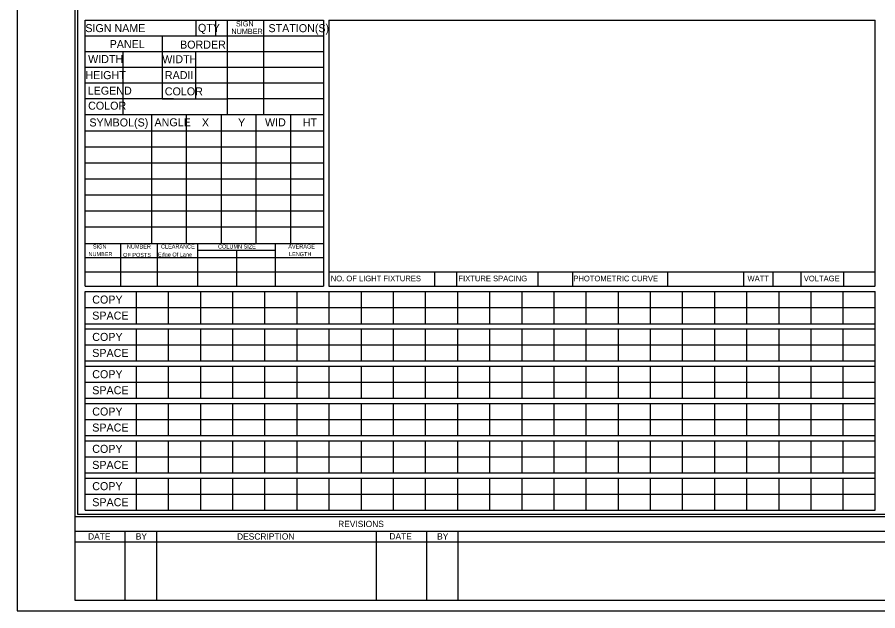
# Model space of a CAD drawing. Extents: x 17890628 to 17891459, y 17897314 to 17897992.
# Drawn here: x 17890701.3 to 17890765.8, y 17897413.7 to 17897458.2 of the extents above; entities that cross this region are included whole.
import ezdxf

# ---------------------------------------------------------------- set-up
doc = ezdxf.new("R2010")
doc.units = 0
for name, color, linetype in [('PlotBorder_dp', 7, 'Continuous'), ('SheetBorder_dp', 7, 'Continuous'), ('SheetLines_dp', 7, 'Continuous'), ('SheetLinesMisc2_dp', 7, 'Continuous'), ('TextMinor', 7, 'Continuous'), ('TextMisc', 7, 'Continuous')]:
    doc.layers.add(name, color=color, linetype=linetype)

msp = doc.modelspace()

# ---------------------------------------------------------------- linework, layer by layer
at = {"layer": 'PlotBorder_dp'}
msp.add_lwpolyline([(17890701.346, 17897413.687), (17890830.745, 17897413.687), (17890830.745, 17897496.818), (17890701.346, 17897496.818)], close=True, dxfattribs=at)
at = {"layer": 'SheetBorder_dp'}
for p, q in [((17890705.659, 17897496.034), (17890705.659, 17897414.472)), ((17890705.659, 17897420.746), (17890826.432, 17897420.746)), ((17890705.659, 17897414.472), (17890826.432, 17897414.472))]:
    msp.add_line(p, q, dxfattribs=at)
at = {"layer": 'SheetLines_dp'}
for p, q in [((17890705.659, 17897419.648), (17890769.182, 17897419.648)), ((17890709.424, 17897419.648), (17890709.424, 17897414.472)), ((17890711.776, 17897419.648), (17890711.776, 17897414.472)), ((17890728.245, 17897419.648), (17890728.245, 17897414.472)), ((17890732.01, 17897419.648), (17890732.01, 17897414.472)), ((17890734.362, 17897419.648), (17890734.362, 17897414.472)), ((17890705.659, 17897418.864), (17890769.182, 17897418.864))]:
    msp.add_line(p, q, dxfattribs=at)
at = {"layer": 'SheetLinesMisc2_dp'}
for p, q in [((17890705.872, 17897495.849), (17890705.872, 17897420.931)), ((17890706.45, 17897438.022), (17890706.45, 17897457.96)), ((17890706.45, 17897457.96), (17890724.295, 17897457.96)), ((17890714.721, 17897457.96), (17890714.721, 17897456.783)), ((17890716.203, 17897457.96), (17890716.203, 17897456.783)), ((17890717.086, 17897457.96), (17890717.086, 17897450.894)), ((17890719.801, 17897457.96), (17890719.801, 17897450.894)), ((17890724.295, 17897457.96), (17890724.295, 17897438.022)), ((17890724.706, 17897457.96), (17890765.638, 17897457.96)), ((17890724.706, 17897457.96), (17890724.706, 17897438.051)), ((17890765.638, 17897438.051), (17890765.638, 17897457.962)), ((17890706.45, 17897456.783), (17890724.295, 17897456.783)), ((17890712.217, 17897456.783), (17890712.217, 17897452.059)), ((17890706.45, 17897455.605), (17890724.295, 17897455.605)), ((17890709.27, 17897455.605), (17890709.27, 17897450.894)), ((17890714.706, 17897455.592), (17890714.706, 17897452.059)), ((17890706.45, 17897454.427), (17890724.295, 17897454.427)), ((17890706.45, 17897453.25), (17890724.295, 17897453.25)), ((17890706.45, 17897452.072), (17890713.068, 17897452.072)), ((17890712.217, 17897452.059), (17890717.086, 17897452.059)), ((17890717.086, 17897452.072), (17890724.295, 17897452.072)), ((17890706.45, 17897450.894), (17890724.295, 17897450.894)), ((17890711.405, 17897450.871), (17890711.405, 17897441.227)), ((17890714.013, 17897450.871), (17890714.013, 17897441.227)), ((17890716.62, 17897450.871), (17890716.62, 17897441.227)), ((17890719.228, 17897450.871), (17890719.228, 17897441.227)), ((17890721.835, 17897450.871), (17890721.835, 17897441.138)), ((17890706.454, 17897449.668), (17890724.295, 17897449.668)), ((17890706.454, 17897448.466), (17890724.295, 17897448.466)), ((17890706.454, 17897447.263), (17890724.295, 17897447.263)), ((17890706.454, 17897446.061), (17890724.295, 17897446.061)), ((17890706.454, 17897444.861), (17890724.295, 17897444.861)), ((17890706.454, 17897443.661), (17890724.295, 17897443.661)), ((17890706.454, 17897442.461), (17890724.295, 17897442.461)), ((17890706.45, 17897441.227), (17890724.295, 17897441.227)), ((17890706.45, 17897441.227), (17890724.295, 17897441.227)), ((17890709.098, 17897441.227), (17890709.098, 17897438.022)), ((17890711.835, 17897441.227), (17890711.835, 17897438.022)), ((17890714.857, 17897441.227), (17890714.857, 17897438.022)), ((17890720.676, 17897441.227), (17890720.676, 17897438.022)), ((17890714.857, 17897440.717), (17890720.672, 17897440.717)), ((17890717.778, 17897440.717), (17890717.778, 17897438.022)), ((17890706.45, 17897440.159), (17890724.295, 17897440.159)), ((17890706.45, 17897439.091), (17890724.295, 17897439.091)), ((17890724.706, 17897439.091), (17890765.638, 17897439.091)), ((17890732.613, 17897439.091), (17890732.613, 17897438.023)), ((17890734.269, 17897439.091), (17890734.269, 17897438.023)), ((17890740.364, 17897439.091), (17890740.364, 17897438.023)), ((17890742.958, 17897439.091), (17890742.958, 17897438.023)), ((17890750.085, 17897439.091), (17890750.085, 17897438.023)), ((17890755.773, 17897439.091), (17890755.773, 17897438.023)), ((17890757.969, 17897439.091), (17890757.969, 17897438.023)), ((17890760.087, 17897439.091), (17890760.087, 17897438.023)), ((17890763.275, 17897439.091), (17890763.275, 17897438.023)), ((17890706.45, 17897438.022), (17890724.295, 17897438.022)), ((17890724.706, 17897438.051), (17890724.706, 17897438.024)), ((17890724.706, 17897438.023), (17890765.638, 17897438.023)), ((17890706.449, 17897437.612), (17890765.638, 17897437.612)), ((17890706.449, 17897421.223), (17890706.449, 17897437.612)), ((17890710.259, 17897437.612), (17890710.259, 17897435.207)), ((17890712.668, 17897437.612), (17890712.668, 17897435.207)), ((17890715.075, 17897437.612), (17890715.075, 17897435.207)), ((17890717.483, 17897437.612), (17890717.483, 17897435.207)), ((17890719.89, 17897437.612), (17890719.89, 17897435.207)), ((17890722.298, 17897437.612), (17890722.298, 17897435.207)), ((17890724.706, 17897437.612), (17890724.706, 17897435.207)), ((17890727.114, 17897437.612), (17890727.114, 17897435.207)), ((17890729.521, 17897437.612), (17890729.521, 17897435.207)), ((17890731.929, 17897437.612), (17890731.929, 17897435.207)), ((17890734.337, 17897437.612), (17890734.337, 17897435.207)), ((17890736.745, 17897437.612), (17890736.745, 17897435.207)), ((17890739.153, 17897437.612), (17890739.153, 17897435.207)), ((17890741.56, 17897437.612), (17890741.56, 17897435.207)), ((17890743.969, 17897437.612), (17890743.969, 17897435.207)), ((17890746.376, 17897437.612), (17890746.376, 17897435.207)), ((17890748.784, 17897437.612), (17890748.784, 17897435.207)), ((17890751.191, 17897437.612), (17890751.191, 17897435.207)), ((17890753.6, 17897437.612), (17890753.6, 17897435.207)), ((17890756.007, 17897437.612), (17890756.007, 17897435.207)), ((17890758.415, 17897437.612), (17890758.415, 17897435.207)), ((17890760.822, 17897437.612), (17890760.822, 17897435.207)), ((17890763.231, 17897437.612), (17890763.231, 17897435.207)), ((17890765.638, 17897421.223), (17890765.638, 17897437.612)), ((17890706.449, 17897436.411), (17890765.638, 17897436.411)), ((17890706.449, 17897435.207), (17890765.638, 17897435.207)), ((17890706.449, 17897434.815), (17890765.638, 17897434.815)), ((17890710.259, 17897434.815), (17890710.259, 17897432.41)), ((17890712.668, 17897434.815), (17890712.668, 17897432.41)), ((17890715.075, 17897434.815), (17890715.075, 17897432.41)), ((17890717.483, 17897434.815), (17890717.483, 17897432.41)), ((17890719.89, 17897434.815), (17890719.89, 17897432.41)), ((17890722.298, 17897434.815), (17890722.298, 17897432.41)), ((17890724.706, 17897434.815), (17890724.706, 17897432.41)), ((17890727.114, 17897434.815), (17890727.114, 17897432.41)), ((17890729.521, 17897434.815), (17890729.521, 17897432.41)), ((17890731.929, 17897434.815), (17890731.929, 17897432.41)), ((17890734.337, 17897434.815), (17890734.337, 17897432.41)), ((17890736.745, 17897434.815), (17890736.745, 17897432.41)), ((17890739.153, 17897434.815), (17890739.153, 17897432.41)), ((17890741.56, 17897434.815), (17890741.56, 17897432.41)), ((17890743.969, 17897434.815), (17890743.969, 17897432.41)), ((17890746.376, 17897434.815), (17890746.376, 17897432.41)), ((17890748.784, 17897434.815), (17890748.784, 17897432.41)), ((17890751.191, 17897434.815), (17890751.191, 17897432.41)), ((17890753.6, 17897434.815), (17890753.6, 17897432.41)), ((17890756.007, 17897434.815), (17890756.007, 17897432.41)), ((17890758.415, 17897434.815), (17890758.415, 17897432.41)), ((17890760.822, 17897434.815), (17890760.822, 17897432.41)), ((17890763.231, 17897434.815), (17890763.231, 17897432.41)), ((17890706.449, 17897433.613), (17890765.638, 17897433.613)), ((17890706.449, 17897432.41), (17890765.638, 17897432.41)), ((17890706.449, 17897432.018), (17890765.638, 17897432.018)), ((17890710.259, 17897432.018), (17890710.259, 17897429.614)), ((17890712.668, 17897432.018), (17890712.668, 17897429.614)), ((17890715.075, 17897432.018), (17890715.075, 17897429.614)), ((17890717.483, 17897432.018), (17890717.483, 17897429.614)), ((17890719.89, 17897432.018), (17890719.89, 17897429.614)), ((17890722.298, 17897432.018), (17890722.298, 17897429.614)), ((17890724.706, 17897432.018), (17890724.706, 17897429.614)), ((17890727.114, 17897432.018), (17890727.114, 17897429.614)), ((17890729.521, 17897432.018), (17890729.521, 17897429.614)), ((17890731.929, 17897432.018), (17890731.929, 17897429.614)), ((17890734.337, 17897432.018), (17890734.337, 17897429.614)), ((17890736.745, 17897432.018), (17890736.745, 17897429.614)), ((17890739.153, 17897432.018), (17890739.153, 17897429.614)), ((17890741.56, 17897432.018), (17890741.56, 17897429.614)), ((17890743.969, 17897432.018), (17890743.969, 17897429.614)), ((17890746.376, 17897432.018), (17890746.376, 17897429.614)), ((17890748.784, 17897432.018), (17890748.784, 17897429.614)), ((17890751.191, 17897432.018), (17890751.191, 17897429.614)), ((17890753.6, 17897432.018), (17890753.6, 17897429.614)), ((17890756.007, 17897432.018), (17890756.007, 17897429.614)), ((17890758.415, 17897432.018), (17890758.415, 17897429.614)), ((17890760.822, 17897432.018), (17890760.822, 17897429.614)), ((17890763.231, 17897432.018), (17890763.231, 17897429.614)), ((17890706.449, 17897430.816), (17890765.638, 17897430.816)), ((17890706.449, 17897429.614), (17890765.638, 17897429.614)), ((17890706.449, 17897429.221), (17890765.638, 17897429.221)), ((17890710.259, 17897429.221), (17890710.259, 17897426.817)), ((17890712.668, 17897429.221), (17890712.668, 17897426.817)), ((17890715.075, 17897429.221), (17890715.075, 17897426.817)), ((17890717.483, 17897429.221), (17890717.483, 17897426.817)), ((17890719.89, 17897429.221), (17890719.89, 17897426.817)), ((17890722.298, 17897429.221), (17890722.298, 17897426.817)), ((17890724.706, 17897429.221), (17890724.706, 17897426.817)), ((17890727.114, 17897429.221), (17890727.114, 17897426.817)), ((17890729.521, 17897429.221), (17890729.521, 17897426.817)), ((17890731.929, 17897429.221), (17890731.929, 17897426.817)), ((17890734.337, 17897429.221), (17890734.337, 17897426.817)), ((17890736.745, 17897429.221), (17890736.745, 17897426.817)), ((17890739.153, 17897429.221), (17890739.153, 17897426.817)), ((17890741.56, 17897429.221), (17890741.56, 17897426.817)), ((17890743.969, 17897429.221), (17890743.969, 17897426.817)), ((17890746.376, 17897429.221), (17890746.376, 17897426.817)), ((17890748.784, 17897429.221), (17890748.784, 17897426.817)), ((17890751.191, 17897429.221), (17890751.191, 17897426.817)), ((17890753.6, 17897429.221), (17890753.6, 17897426.817)), ((17890756.007, 17897429.221), (17890756.007, 17897426.817)), ((17890758.415, 17897429.221), (17890758.415, 17897426.817)), ((17890760.822, 17897429.221), (17890760.822, 17897426.817)), ((17890763.231, 17897429.221), (17890763.231, 17897426.817)), ((17890706.449, 17897428.02), (17890765.638, 17897428.02)), ((17890706.449, 17897426.817), (17890765.638, 17897426.817)), ((17890706.449, 17897426.424), (17890765.638, 17897426.424)), ((17890710.259, 17897426.424), (17890710.259, 17897424.02)), ((17890712.668, 17897426.424), (17890712.668, 17897424.02)), ((17890715.075, 17897426.424), (17890715.075, 17897424.02)), ((17890717.483, 17897426.424), (17890717.483, 17897424.02)), ((17890719.89, 17897426.424), (17890719.89, 17897424.02)), ((17890722.298, 17897426.424), (17890722.298, 17897424.02)), ((17890724.706, 17897426.424), (17890724.706, 17897424.02)), ((17890727.114, 17897426.424), (17890727.114, 17897424.02)), ((17890729.521, 17897426.424), (17890729.521, 17897424.02)), ((17890731.929, 17897426.424), (17890731.929, 17897424.02)), ((17890734.337, 17897426.424), (17890734.337, 17897424.02)), ((17890736.745, 17897426.424), (17890736.745, 17897424.02)), ((17890739.153, 17897426.424), (17890739.153, 17897424.02)), ((17890741.56, 17897426.424), (17890741.56, 17897424.02)), ((17890743.969, 17897426.424), (17890743.969, 17897424.02)), ((17890746.376, 17897426.424), (17890746.376, 17897424.02)), ((17890748.784, 17897426.424), (17890748.784, 17897424.02)), ((17890751.191, 17897426.424), (17890751.191, 17897424.02)), ((17890753.6, 17897426.424), (17890753.6, 17897424.02)), ((17890756.007, 17897426.424), (17890756.007, 17897424.02)), ((17890758.415, 17897426.424), (17890758.415, 17897424.02)), ((17890760.822, 17897426.424), (17890760.822, 17897424.02)), ((17890763.231, 17897426.424), (17890763.231, 17897424.02)), ((17890706.449, 17897425.222), (17890765.638, 17897425.222)), ((17890706.449, 17897424.02), (17890765.638, 17897424.02)), ((17890706.449, 17897423.628), (17890765.638, 17897423.628)), ((17890710.259, 17897423.628), (17890710.259, 17897421.223)), ((17890712.668, 17897423.628), (17890712.668, 17897421.223)), ((17890715.075, 17897423.628), (17890715.075, 17897421.223)), ((17890717.483, 17897423.628), (17890717.483, 17897421.223)), ((17890719.89, 17897423.628), (17890719.89, 17897421.223)), ((17890722.298, 17897423.628), (17890722.298, 17897421.223)), ((17890724.706, 17897423.628), (17890724.706, 17897421.223)), ((17890727.114, 17897423.628), (17890727.114, 17897421.223)), ((17890729.521, 17897423.628), (17890729.521, 17897421.223)), ((17890731.929, 17897423.628), (17890731.929, 17897421.223)), ((17890734.337, 17897423.628), (17890734.337, 17897421.223)), ((17890736.745, 17897423.628), (17890736.745, 17897421.223)), ((17890739.153, 17897423.628), (17890739.153, 17897421.223)), ((17890741.56, 17897423.628), (17890741.56, 17897421.223)), ((17890743.969, 17897423.628), (17890743.969, 17897421.223)), ((17890746.376, 17897423.628), (17890746.376, 17897421.223)), ((17890748.784, 17897423.628), (17890748.784, 17897421.223)), ((17890751.191, 17897423.628), (17890751.191, 17897421.223)), ((17890753.6, 17897423.628), (17890753.6, 17897421.223)), ((17890756.007, 17897423.628), (17890756.007, 17897421.223)), ((17890758.415, 17897423.628), (17890758.415, 17897421.223)), ((17890760.822, 17897423.628), (17890760.822, 17897421.223)), ((17890763.231, 17897423.628), (17890763.231, 17897421.223)), ((17890706.449, 17897422.425), (17890765.638, 17897422.425)), ((17890705.872, 17897420.931), (17890826.223, 17897420.931)), ((17890706.449, 17897421.223), (17890765.638, 17897421.223))]:
    msp.add_line(p, q, dxfattribs=at)

# ---------------------------------------------------------------- texts
at = {"layer": 'TextMinor'}
for s, height, p in [('SIGN', 0.3921, (17890717.741, 17897457.488)), ('SIGN NAME', 0.5999, (17890706.45, 17897457.059)), ('QTY', 0.5999, (17890714.892, 17897457.078)), ('NUMBER', 0.3921, (17890717.4, 17897456.918)), ('STATION(S)', 0.5999, (17890720.176, 17897457.055)), ('PANEL', 0.5999, (17890708.274, 17897455.862)), ('BORDER', 0.5999, (17890713.551, 17897455.821)), ('WIDTH', 0.5999, (17890706.661, 17897454.741)), ('WIDTH', 0.5999, (17890712.217, 17897454.729)), ('HEIGHT', 0.5999, (17890706.45, 17897453.534)), ('RADII', 0.5999, (17890712.414, 17897453.536)), ('LEGEND', 0.5999, (17890706.63, 17897452.369)), ('COLOR', 0.5999, (17890712.409, 17897452.318)), ('COLOR', 0.5999, (17890706.661, 17897451.245)), ('SYMBOL(S)', 0.5999, (17890706.757, 17897449.987)), ('ANGLE', 0.5999, (17890711.635, 17897449.999)), ('WID', 0.5999, (17890719.916, 17897449.999)), ('X', 0.6, (17890715.186, 17897449.987)), ('Y', 0.6, (17890717.897, 17897449.987)), ('HT', 0.5999, (17890722.743, 17897449.988)), ('SIGN', 0.3, (17890707.022, 17897440.839)), ('NUMBER', 0.3, (17890709.569, 17897440.835)), ('CLEARANCE', 0.3, (17890712.123, 17897440.838)), ('COLUMN SIZE', 0.29998, (17890716.398, 17897440.838)), ('AVERAGE', 0.3, (17890721.659, 17897440.838)), ('NUMBER', 0.3, (17890706.686, 17897440.269)), ('OF POSTS', 0.3, (17890709.285, 17897440.212)), ('Edge Of Lane', 0.29998, (17890711.892, 17897440.234)), ('LENGTH', 0.3, (17890721.716, 17897440.269)), ('NO. OF LIGHT FIXTURES', 0.42516, (17890724.844, 17897438.381)), ('FIXTURE SPACING', 0.42516, (17890734.417, 17897438.381)), ('PHOTOMETRIC CURVE', 0.42516, (17890743.026, 17897438.381)), ('WATT', 0.4252, (17890756.078, 17897438.381)), ('VOLTAGE', 0.4252, (17890760.299, 17897438.381)), ('COPY', 0.6, (17890706.969, 17897436.713)), ('SPACE', 0.6, (17890706.969, 17897435.511)), ('COPY', 0.6, (17890706.969, 17897433.915)), ('SPACE', 0.6, (17890706.969, 17897432.713)), ('COPY', 0.6, (17890706.969, 17897431.119)), ('SPACE', 0.6, (17890706.969, 17897429.917)), ('COPY', 0.6, (17890706.969, 17897428.321)), ('SPACE', 0.6, (17890706.969, 17897427.12)), ('COPY', 0.6, (17890706.969, 17897425.524)), ('SPACE', 0.6, (17890706.969, 17897424.322)), ('COPY', 0.6, (17890706.969, 17897422.728)), ('SPACE', 0.6, (17890706.969, 17897421.526))]:
    msp.add_text(s, height=height, dxfattribs=at).set_placement(p)
at = {"layer": 'TextMisc'}
for s, p in [('REVISIONS', (17890725.399, 17897419.961)), ('BY', (17890710.232, 17897419.028)), ('BY', (17890732.818, 17897419.028))]:
    msp.add_text(s, height=0.4705, dxfattribs=at).set_placement(p)
for s, height, rotation, p in [('DATE', 0.4705, 359.86925, (17890706.656, 17897419.028)), ('DESCRIPTION', 0.47045, 0.04975, (17890717.823, 17897419.02)), ('DATE', 0.4705, 359.86925, (17890729.242, 17897419.035))]:
    msp.add_text(s, height=height, rotation=rotation, dxfattribs=at).set_placement(p)

doc.saveas('drawing.dxf')
